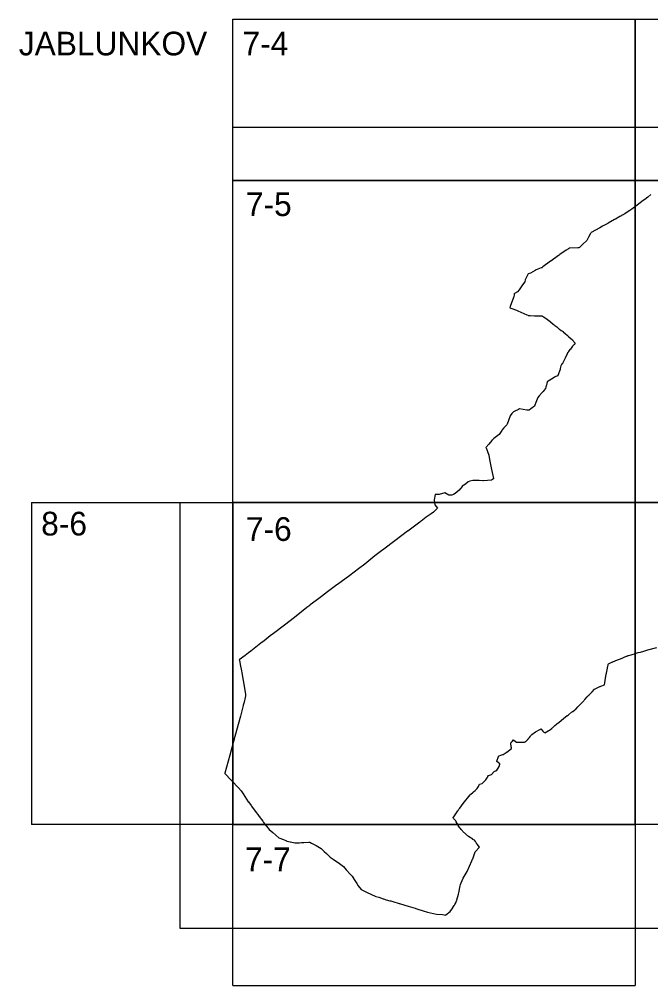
# Model space of a CAD drawing. Extents: x -447352 to -425530, y -1135906 to -1125104.
# Drawn here: x -440181.2 to -439936.1, y -1126653.4 to -1126278.4 of the extents above; entities that cross this region are included whole.
import ezdxf

# ---------------------------------------------------------------- set-up
doc = ezdxf.new("R2010")
doc.units = 0
for name, color, linetype in [('Vrstva 1', 7, 'Continuous'), ('Vrstva 10', 7, 'Continuous'), ('Vrstva 4', 7, 'Continuous')]:
    doc.layers.add(name, color=color, linetype=linetype)

msp = doc.modelspace()

# ---------------------------------------------------------------- linework, layer by layer
at = {"layer": 'Vrstva 1'}
for points in [[(-439936.01, -1126346.44), (-439937.22, -1126347.4), (-439937.22, -1126347.4), (-439938.37, -1126348.27), (-439938.94, -1126348.7), (-439939.52, -1126349.14), (-439939.68, -1126349.26), (-439941.81, -1126350.9), (-439942.88, -1126351.72), (-439943.35, -1126352.06), (-439944.11, -1126352.57), (-439944.36, -1126352.73), (-439944.95, -1126353.12), (-439944.99, -1126353.15), (-439945.2, -1126353.29), (-439946.11, -1126353.89), (-439946.12, -1126353.89), (-439946.59, -1126354.15), (-439946.74, -1126354.23), (-439946.92, -1126354.33), (-439947.38, -1126354.58), (-439947.56, -1126354.69), (-439947.72, -1126354.78), (-439947.82, -1126354.84), (-439948.06, -1126354.98), (-439949.72, -1126355.92), (-439949.89, -1126356.01), (-439950.12, -1126356.14), (-439952.59, -1126357.54), (-439952.71, -1126357.61), (-439954.82, -1126358.74), (-439955.84, -1126359.29), (-439959.18, -1126361.1), (-439959.35, -1126361.4), (-439959.41, -1126361.51), (-439960.19, -1126362.97), (-439960.87, -1126364.29), (-439961.01, -1126364.42), (-439961.1, -1126364.5), (-439962.24, -1126365.54), (-439963.75, -1126366.92), (-439963.92, -1126367.07), (-439963.92, -1126367.08), (-439964.39, -1126367.09), (-439967.58, -1126367.18), (-439967.59, -1126367.18), (-439968.02, -1126367.47), (-439968.85, -1126368.04), (-439971.32, -1126369.7), (-439971.36, -1126369.72), (-439971.6, -1126369.9), (-439971.87, -1126370.1), (-439974.85, -1126372.23), (-439974.92, -1126372.28), (-439977.92, -1126374.46), (-439978.39, -1126374.8), (-439978.55, -1126374.86), (-439980.49, -1126375.58), (-439980.5, -1126375.58), (-439980.89, -1126375.82), (-439982.77, -1126376.98), (-439983.69, -1126377.19), (-439983.94, -1126377.7), (-439984.7, -1126379.21), (-439984.71, -1126379.22), (-439984.78, -1126379.48), (-439984.98, -1126380.32), (-439985.81, -1126381.43), (-439987.18, -1126383.38), (-439987.74, -1126384.19), (-439987.77, -1126384.21), (-439988.93, -1126384.85), (-439989.03, -1126384.91), (-439989.1, -1126385.3), (-439989.25, -1126386.11), (-439989.3, -1126386.3), (-439990.59, -1126389.88), (-439990.76, -1126390.36), (-439990.73, -1126390.35), (-439990.71, -1126390.34), (-439990.03, -1126390.6), (-439988.22, -1126391.26), (-439987.6, -1126391.55), (-439985.31, -1126392.63), (-439985.29, -1126392.63), (-439984.13, -1126393.1), (-439983.66, -1126393.28), (-439983.63, -1126393.29), (-439983.2, -1126393.32), (-439983.06, -1126393.33), (-439982.84, -1126393.35), (-439981.24, -1126393.45), (-439980.2, -1126393.52), (-439979.15, -1126393.49), (-439978.31, -1126393.46), (-439978.3, -1126393.46), (-439978.02, -1126393.61), (-439977.65, -1126393.87), (-439977.1, -1126394.25), (-439976.71, -1126394.53), (-439975.15, -1126395.67), (-439974.98, -1126395.79), (-439973.87, -1126396.71), (-439973.48, -1126397.03), (-439973.3, -1126397.18), (-439972.55, -1126397.79), (-439972.28, -1126398.02), (-439971.68, -1126398.51), (-439971.46, -1126398.69), (-439970.82, -1126399.11), (-439970.07, -1126399.61), (-439970.04, -1126399.63), (-439969.28, -1126400.31), (-439968.4, -1126401.09), (-439967.96, -1126401.47), (-439966.95, -1126402.36), (-439966.69, -1126402.59), (-439966.64, -1126402.64), (-439966.54, -1126402.74), (-439966.53, -1126402.75), (-439966.44, -1126402.85), (-439966.41, -1126402.88), (-439965.36, -1126404.11), (-439965.37, -1126404.12), (-439965.81, -1126404.61), (-439965.87, -1126404.68), (-439966.44, -1126405.31), (-439967.26, -1126406.37), (-439967.43, -1126406.58), (-439967.99, -1126407.3), (-439968.29, -1126407.83), (-439968.31, -1126407.87), (-439968.32, -1126407.89), (-439968.45, -1126408.17), (-439969.25, -1126409.84), (-439969.56, -1126410.48), (-439970.18, -1126411.77), (-439970.29, -1126412.01), (-439970.3, -1126412.01), (-439970.34, -1126412.04), (-439970.63, -1126412.24), (-439970.71, -1126412.28), (-439970.76, -1126412.38), (-439970.85, -1126412.58), (-439970.94, -1126412.86), (-439971.11, -1126413.42), (-439971.12, -1126413.44), (-439971.24, -1126413.94), (-439971.26, -1126414.01), (-439971.25, -1126414.07), (-439971.24, -1126414.15), (-439971.24, -1126414.22), (-439971.25, -1126414.27), (-439972.13, -1126416.6), (-439972.15, -1126416.65), (-439972.17, -1126416.69), (-439972.18, -1126416.7), (-439972.88, -1126417), (-439973.13, -1126417.11), (-439973.6, -1126417.35), (-439976.21, -1126419.04), (-439976.21, -1126419.04), (-439976.58, -1126420.35), (-439976.66, -1126420.61), (-439976.77, -1126421.03), (-439976.83, -1126421.24), (-439976.83, -1126421.25), (-439976.82, -1126421.25), (-439976.65, -1126421.41), (-439976.66, -1126421.42), (-439977.02, -1126421.81), (-439977.82, -1126422.81), (-439977.83, -1126422.82), (-439978.04, -1126423.07), (-439978.04, -1126423.08), (-439978.16, -1126423.23), (-439979.32, -1126424.58), (-439979.86, -1126425.21), (-439980.62, -1126427.16), (-439981, -1126428.18), (-439981.13, -1126428.53), (-439982.66, -1126429.63), (-439983.28, -1126430.07), (-439983.46, -1126430.11), (-439983.48, -1126430.11), (-439984.11, -1126430.02), (-439986.95, -1126429.6), (-439987.44, -1126429.84), (-439988.77, -1126430.48), (-439989.31, -1126430.74), (-439989.34, -1126430.77), (-439989.77, -1126431.18), (-439989.94, -1126431.4), (-439990.6, -1126432.25), (-439990.6, -1126432.26), (-439991.27, -1126434.06), (-439991.84, -1126435.56), (-439991.84, -1126435.56), (-439991.98, -1126435.78), (-439992.31, -1126436.15), (-439993.03, -1126436.95), (-439993.73, -1126437.72), (-439993.74, -1126437.74), (-439993.87, -1126437.93), (-439994.94, -1126439.5), (-439995.41, -1126439.88), (-439996.98, -1126441.14), (-439997.65, -1126441.68), (-439997.75, -1126441.76), (-439997.78, -1126441.8), (-439998.9, -1126443.23), (-440000.04, -1126444.54), (-439999.89, -1126444.71), (-439999.88, -1126444.74), (-439999.88, -1126444.75), (-439998.87, -1126447.51), (-439998.59, -1126449.17), (-439998.27, -1126451.12), (-439997.86, -1126453.08), (-439997.13, -1126456.58), (-439997.09, -1126456.78), (-439997.74, -1126457.12), (-439997.86, -1126457.19), (-440001.03, -1126457.45), (-440001.19, -1126457.45), (-440002.68, -1126457.42), (-440005.07, -1126457.4), (-440006.35, -1126457.67), (-440006.95, -1126457.94), (-440007.93, -1126458.74), (-440009.23, -1126459.61), (-440009.32, -1126459.72), (-440010.48, -1126461.14), (-440011.93, -1126462.48), (-440012.62, -1126462.8), (-440013.22, -1126463.08), (-440014.39, -1126463.01), (-440016, -1126462.16), (-440018.24, -1126462.83), (-440019.72, -1126462.8), (-440020.1, -1126464.91), (-440020.11, -1126464.93), (-440020.12, -1126465.02), (-440019.83, -1126466.83), (-440018.86, -1126468.15), (-440018.85, -1126468.17), (-440019.59, -1126468.92), (-440020.2, -1126469.48), (-440020.45, -1126469.71), (-440021.25, -1126470.34), (-440023.18, -1126471.57), (-440023.24, -1126471.61), (-440025.21, -1126473.14), (-440025.27, -1126473.18), (-440025.76, -1126473.56), (-440030.42, -1126477.02), (-440030.45, -1126477.05), (-440035.4, -1126480.81), (-440039.66, -1126484.06), (-440040.54, -1126484.72), (-440043.11, -1126486.66), (-440047.11, -1126489.79), (-440049.55, -1126491.66), (-440052.86, -1126494.19), (-440052.91, -1126494.23), (-440057.7, -1126497.74), (-440057.93, -1126497.92), (-440061.54, -1126500.6), (-440063.93, -1126502.42), (-440065.9, -1126503.9), (-440068.22, -1126505.65), (-440068.45, -1126505.82), (-440069.58, -1126506.71), (-440074.4, -1126510.51), (-440078.29, -1126513.46), (-440082.51, -1126516.71), (-440083.8, -1126517.71), (-440086.19, -1126519.59), (-440087.37, -1126520.51), (-440091.31, -1126523.56), (-440092.24, -1126524.27), (-440093.48, -1126525.23), (-440095.8, -1126527.03), (-440095.8, -1126527.03), (-440095.76, -1126527.21), (-440095.47, -1126528.59), (-440095.44, -1126528.75), (-440094.91, -1126531.29), (-440094.75, -1126532.02), (-440094.75, -1126532.06), (-440093.82, -1126537.94), (-440093.81, -1126537.97), (-440093.51, -1126539.7), (-440093.51, -1126539.72), (-440093.45, -1126540.09), (-440093.39, -1126540.51), (-440093.42, -1126540.88), (-440093.57, -1126541.61), (-440093.95, -1126543.4), (-440094.24, -1126544.58), (-440094.26, -1126544.63), (-440095.37, -1126548.8), (-440097.47, -1126556.68), (-440099.46, -1126563.9), (-440101.39, -1126571), (-440101.4, -1126571.04), (-440096.12, -1126576.64), (-440095.07, -1126577.77), (-440094.31, -1126578.99), (-440092.29, -1126582.05), (-440092.24, -1126582.12), (-440091.23, -1126583.53), (-440091.07, -1126583.74), (-440089.19, -1126586.22), (-440088.62, -1126586.96), (-440088.59, -1126587), (-440088.07, -1126587.72), (-440086.69, -1126589.62), (-440086.36, -1126590.07), (-440084.21, -1126592.79), (-440082.81, -1126594.01), (-440080.41, -1126595.99), (-440078.67, -1126596.74), (-440077.48, -1126597.26), (-440077.35, -1126597.31), (-440076.02, -1126597.59), (-440075.88, -1126597.62), (-440074.26, -1126597.95), (-440074.23, -1126597.95), (-440073.27, -1126597.93), (-440072.89, -1126597.93), (-440072.37, -1126597.92), (-440071.69, -1126597.91), (-440070.78, -1126597.87), (-440068.83, -1126597.71), (-440068.38, -1126597.78), (-440067.72, -1126598.13), (-440066, -1126599.08), (-440064.04, -1126600.18), (-440063.52, -1126600.66), (-440062.8, -1126601.34), (-440062, -1126602.09), (-440060.68, -1126603.39), (-440060.54, -1126603.49), (-440059.35, -1126604.34), (-440056.94, -1126606.05), (-440055.3, -1126607.23), (-440054.25, -1126608.41), (-440052.61, -1126610.23), (-440051.97, -1126610.94), (-440051.61, -1126611.53), (-440051.15, -1126612.27), (-440050.21, -1126613.74), (-440049.58, -1126614.66), (-440048.54, -1126616.1), (-440047.47, -1126616.61), (-440046.09, -1126617.26), (-440044.78, -1126617.87), (-440042.81, -1126618.76), (-440041.68, -1126619.11), (-440039.96, -1126619.68), (-440039.81, -1126619.73), (-440038.72, -1126620.05), (-440037.3, -1126620.47), (-440037.29, -1126620.47), (-440037.08, -1126620.53), (-440037.02, -1126620.55), (-440036.16, -1126620.81), (-440033.77, -1126621.5), (-440033.65, -1126621.54), (-440033.17, -1126621.68), (-440030.24, -1126622.55), (-440027.55, -1126623.38), (-440027.21, -1126623.48), (-440026.45, -1126623.71), (-440024.44, -1126624.33), (-440022.71, -1126624.88), (-440019.25, -1126625.62)], [(-440019.25, -1126625.62), (-440016.86, -1126625.81), (-440015.66, -1126626.04), (-440015.55, -1126625.95), (-440013.97, -1126624.68), (-440012.94, -1126623.2), (-440012.83, -1126623.05), (-440012.31, -1126622.29), (-440012.2, -1126622.12), (-440012.06, -1126621.89), (-440011.68, -1126621.26), (-440011.41, -1126620.43), (-440011.39, -1126620.36), (-440011.37, -1126620.31), (-440011.34, -1126620.2), (-440011.31, -1126620.11), (-440011.31, -1126620.1), (-440010.68, -1126617.9), (-440010.54, -1126617.38), (-440010.09, -1126614.63), (-440010.09, -1126614.63), (-440009.9, -1126614.19), (-440009.64, -1126613.57), (-440008.85, -1126611.74), (-440007.28, -1126609.09), (-440005.53, -1126604.96), (-440005.21, -1126604.32), (-440005.17, -1126604.19), (-440004.78, -1126603.09), (-440004.19, -1126601.42), (-440002.51, -1126599.71), (-440003.44, -1126598.47), (-440003.5, -1126598.38), (-440003.55, -1126598.32), (-440003.58, -1126598.28), (-440003.65, -1126598.18), (-440003.7, -1126598.1), (-440003.78, -1126597.98), (-440004.14, -1126597.46), (-440004.51, -1126597), (-440005.08, -1126596.63), (-440005.18, -1126596.57), (-440006.83, -1126595.5), (-440009.02, -1126593.56), (-440009.15, -1126593.39), (-440009.18, -1126593.35), (-440009.26, -1126593.25), (-440009.6, -1126592.83), (-440009.93, -1126592.42), (-440010.19, -1126592.1), (-440010.67, -1126591.51), (-440010.75, -1126591.41), (-440011.25, -1126590.45), (-440011.54, -1126589.89), (-440011.77, -1126589.46), (-440011.82, -1126589.37), (-440011.86, -1126589.32), (-440012.12, -1126589.03), (-440012.32, -1126588.8), (-440012.58, -1126588.51), (-440012.8, -1126588.26), (-440010.94, -1126585.52), (-440010.85, -1126585.4), (-440010.53, -1126584.95), (-440010.21, -1126584.51), (-440008.88, -1126582.68), (-440006.2, -1126579.42), (-440005.85, -1126579.1), (-440005.14, -1126578.4), (-440005.03, -1126578.31), (-440004.84, -1126578.17), (-440004.24, -1126577.69), (-440003.38, -1126576.85), (-440002.97, -1126576.09), (-440002.5, -1126575.22), (-440001.45, -1126574.98), (-440000.05, -1126573.55), (-439999.51, -1126572.7), (-439999.5, -1126572.69), (-439999.5, -1126572.67), (-439999.29, -1126572.34), (-439999.24, -1126572.26), (-439999, -1126571.87), (-439997.84, -1126571.43), (-439996.82, -1126570.25), (-439996.29, -1126570.05), (-439996.17, -1126570), (-439995.75, -1126569.84), (-439995.53, -1126569.45), (-439995.48, -1126569.36), (-439995.31, -1126569.06), (-439994.9, -1126568.32), (-439994.7, -1126567.41), (-439994.7, -1126567.39), (-439994.69, -1126567.38), (-439995.74, -1126566.39), (-439995.76, -1126566.38), (-439995.77, -1126566.36), (-439995.82, -1126566.32), (-439995.17, -1126564.52), (-439995.1, -1126564.32), (-439994.94, -1126564.26), (-439994.21, -1126563.97), (-439993.52, -1126563.7), (-439993.4, -1126563.65), (-439992.19, -1126562.94), (-439992.07, -1126562.86), (-439992.07, -1126562.86), (-439992.06, -1126562.85), (-439991.94, -1126562.78), (-439990.08, -1126561.38), (-439990.08, -1126561.34), (-439990.11, -1126561.18), (-439990.18, -1126560.7), (-439990.24, -1126560.35), (-439990.34, -1126559.73), (-439990.36, -1126559.62), (-439990.38, -1126559.49), (-439990.4, -1126559.32), (-439990.43, -1126559.18), (-439989.89, -1126558.62), (-439989.33, -1126558.05), (-439989.29, -1126558), (-439989.15, -1126558.1), (-439988.15, -1126558.89), (-439987.47, -1126558.9), (-439987.41, -1126558.9), (-439987.16, -1126558.91), (-439987, -1126558.91), (-439985.69, -1126558.93), (-439985.06, -1126558.95), (-439984.79, -1126558.79), (-439984.76, -1126558.77), (-439984.64, -1126558.7), (-439984.5, -1126558.61), (-439984.46, -1126558.58), (-439983.92, -1126557.98), (-439983.81, -1126557.86), (-439983.72, -1126557.76), (-439983.55, -1126557.58), (-439983.47, -1126557.49), (-439983.36, -1126557.37), (-439983.33, -1126557.33), (-439983.3, -1126557.3), (-439983.25, -1126557.24), (-439983.16, -1126557.13), (-439982.76, -1126556.63), (-439982.55, -1126556.37), (-439982.3, -1126556.05), (-439982.19, -1126555.97), (-439980.73, -1126554.9), (-439980.52, -1126554.77), (-439979.16, -1126554), (-439978.76, -1126553.77), (-439978.76, -1126553.77), (-439978.62, -1126553.92), (-439977.91, -1126554.63), (-439977.54, -1126555.01), (-439977.36, -1126555.18), (-439977.21, -1126555.33), (-439977.12, -1126555.29), (-439975.84, -1126554.52), (-439975.75, -1126554.47), (-439974.82, -1126553.91), (-439974.78, -1126553.88), (-439974.45, -1126553.59), (-439974.4, -1126553.55), (-439974.23, -1126553.4), (-439974.22, -1126553.39), (-439974.22, -1126553.39), (-439974.18, -1126553.35), (-439974.14, -1126553.31), (-439973.25, -1126552.5), (-439973.23, -1126552.49), (-439972.64, -1126551.95), (-439972.53, -1126551.86), (-439972.42, -1126551.76), (-439972.42, -1126551.76), (-439972.41, -1126551.76), (-439972.41, -1126551.76), (-439972.41, -1126551.75), (-439972.4, -1126551.75), (-439972.39, -1126551.74), (-439972.39, -1126551.74), (-439972.38, -1126551.73), (-439972.38, -1126551.73), (-439972.37, -1126551.73), (-439972.37, -1126551.73), (-439971.79, -1126551.24), (-439969.8, -1126549.56), (-439968.6, -1126548.71), (-439968.48, -1126548.63), (-439968.43, -1126548.59), (-439968.41, -1126548.58), (-439968.36, -1126548.55), (-439968, -1126548.28), (-439966.76, -1126547.34), (-439966.58, -1126547.2), (-439966.37, -1126547.04), (-439966.35, -1126547.02), (-439965.47, -1126546.35), (-439965.12, -1126546.08), (-439965.07, -1126546.02), (-439964.98, -1126545.92), (-439964.34, -1126545.24), (-439963.44, -1126544.26), (-439962.08, -1126542.85), (-439961.86, -1126542.62), (-439961.61, -1126542.34), (-439960.77, -1126541.39), (-439960.48, -1126541.07), (-439960.28, -1126540.86), (-439959.99, -1126540.54), (-439958.81, -1126539.35), (-439957.88, -1126538.33), (-439955.82, -1126537.32), (-439955.66, -1126537.27), (-439955.46, -1126537.19), (-439954.02, -1126536.7), (-439953.87, -1126535.83), (-439953.71, -1126534.96), (-439953.29, -1126532.59), (-439953.21, -1126532.12), (-439952.88, -1126530.24), (-439952.68, -1126529.36), (-439952.65, -1126529.24), (-439952.6, -1126529.05), (-439952.59, -1126529.01), (-439952.57, -1126528.94), (-439952.56, -1126528.9), (-439952.55, -1126528.85), (-439952.54, -1126528.81), (-439952.53, -1126528.79), (-439952.47, -1126528.58), (-439951.39, -1126528.04), (-439951.1, -1126527.9), (-439951.08, -1126527.89), (-439950.83, -1126527.76), (-439950.78, -1126527.74), (-439949.01, -1126527.02), (-439948.98, -1126527.01), (-439948.95, -1126526.99), (-439948.15, -1126526.68), (-439947.19, -1126526.28), (-439946.38, -1126525.94), (-439945.44, -1126525.55), (-439945.36, -1126525.52), (-439944.75, -1126525.28), (-439944.9, -1126525.44), (-439944.66, -1126525.35), (-439944.17, -1126525.15), (-439943.64, -1126524.99), (-439941.94, -1126524.47), (-439941.35, -1126524.3), (-439940.9, -1126524.18), (-439940.01, -1126523.93), (-439938.7, -1126523.55), (-439937.16, -1126523.09), (-439933.62, -1126522.22)]]:
    msp.add_lwpolyline(points, dxfattribs=at)
at = {"layer": 'Vrstva 10'}
msp.add_lwpolyline([(-439785.86, -1126320.23), (-439785.86, -1126631.21), (-440118.73, -1126631.21), (-440118.73, -1126465.91), (-440098.36, -1126465.91), (-440098.36, -1126340.91), (-440098.36, -1126320.23), (-439785.86, -1126320.23)], dxfattribs=at)
at = {"layer": 'Vrstva 4'}
for p, q in [((-440098.36, -1126278.41), (-439785.86, -1126278.41)), ((-440176.49, -1126465.91), (-440176.49, -1126590.91)), ((-440098.36, -1126653.41), (-439942.11, -1126653.41))]:
    msp.add_line(p, q, dxfattribs=at)
for points in [[(-439942.11, -1126278.41), (-439942.11, -1126340.91), (-440098.36, -1126340.91), (-440098.36, -1126278.41)], [(-439785.86, -1126278.41), (-439785.86, -1126340.91), (-439942.11, -1126340.91), (-439942.11, -1126278.41)], [(-440176.49, -1126465.91), (-440098.36, -1126465.91), (-440098.36, -1126590.91), (-440176.49, -1126590.91)], [(-440098.36, -1126653.41), (-440098.36, -1126590.91), (-439942.11, -1126590.91), (-439942.11, -1126653.41)]]:
    msp.add_lwpolyline(points, dxfattribs=at)
for points in [[(-439942.11, -1126340.91), (-439942.11, -1126465.91), (-440098.36, -1126465.91), (-440098.36, -1126340.91)], [(-439785.86, -1126340.91), (-439785.86, -1126465.91), (-439942.11, -1126465.91), (-439942.11, -1126340.91)], [(-439942.11, -1126465.91), (-439942.11, -1126590.91), (-440098.36, -1126590.91), (-440098.36, -1126465.91)], [(-439785.86, -1126465.91), (-439785.86, -1126590.91), (-439942.11, -1126590.91), (-439942.11, -1126465.91)]]:
    msp.add_lwpolyline(points, close=True, dxfattribs=at)

# ---------------------------------------------------------------- texts
at = {"layer": 'Vrstva 1'}
for s, p in [('JABLUNKOV', (-440181.4, -1126292.41)), ('7-4', (-440094.55, -1126292.41)), ('7-5', (-440093.24, -1126354.75)), ('8-6', (-440172.71, -1126478.72)), ('7-6', (-440093.24, -1126480.82)), ('7-7', (-440093.6, -1126608.99))]:
    msp.add_text(s, height=9.2, dxfattribs=at).set_placement(p)

doc.saveas('drawing.dxf')
